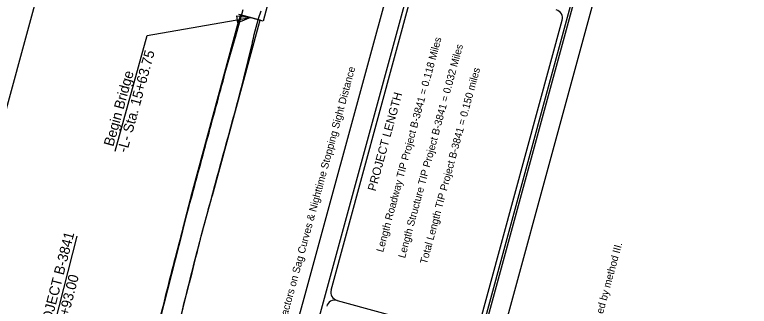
# Model space of a CAD drawing. Extents: x 2076126 to 2079903, y 925480 to 928006.
# Drawn here: x 2079033 to 2079903, y 926068 to 926413 of the extents above; entities that cross this region are included whole.
import ezdxf

# ---------------------------------------------------------------- set-up
doc = ezdxf.new("R2010")
doc.units = 0
for name, color, linetype in [('Default', 7, 'Continuous'), ('Old_Level_3', 7, 'Continuous'), ('Prop EOT', 7, 'Continuous'), ('Prop Horizontal Alignment Curve and Spiral Data', 7, 'Continuous'), ('Prop Roadway Bridge', 7, 'Continuous'), ('Prop Shade Heavy', 7, 'Continuous'), ('Prop Shade Medium', 7, 'Continuous'), ('Sheet Data Field CELL', 7, 'Continuous'), ('Sheet Plot Border Inside CELL', 7, 'Continuous'), ('Sheet Plot Border Outside CELL', 7, 'Continuous'), ('Sheet Title CELL', 7, 'Continuous')]:
    doc.layers.add(name, color=color, linetype=linetype)

msp = doc.modelspace()

# ---------------------------------------------------------------- linework, layer by layer
at = {"layer": 'Default'}
msp.add_line((2079152.14, 926251.6), (2079189.95, 926388.47), dxfattribs=at)
msp.add_lwpolyline([(2079189.95, 926388.47), (2079312.25, 926409.91)], dxfattribs=at)
msp.add_lwpolyline([(2079296.36, 926411.79), (2079312.25, 926409.91), (2079297.55, 926403.59)], close=True, dxfattribs=at)
at = {"layer": 'Old_Level_3'}
for p, q in [((2079282.55, 926344.59), (2079294.11, 926385.17)), ((2079304.56, 926338.12), (2079314.61, 926379.68))]:
    msp.add_line(p, q, dxfattribs=at)
for points in [[(2079294.11, 926385.17), (2079294.48, 926386.49), (2079303.66, 926419.15)], [(2079314.61, 926379.68), (2079314.76, 926380.22), (2079314.9, 926380.86)]]:
    msp.add_lwpolyline(points, dxfattribs=at)
for points in [[(2079314.9, 926380.86), (2079324.11, 926415.38), (2079324.96, 926417.77)], [(2079188.92, 925968.28), (2079196.1, 926009.76), (2079205.39, 926053.24), (2079215.66, 926095.07), (2079226.53, 926137.47), (2079237.81, 926179.58), (2079249.18, 926221.19), (2079260.41, 926263), (2079271.8, 926304.79), (2079282.55, 926344.59)], [(2079212.37, 925965.4), (2079219.2, 926006.07), (2079228.11, 926047.86), (2079238.24, 926089.55), (2079248.89, 926131.69), (2079259.94, 926173.18), (2079271.27, 926214.87), (2079282.61, 926256.56), (2079294.09, 926298.22), (2079304.56, 926338.12)]]:
    msp.add_spline(points, degree=3, dxfattribs=at)
at = {"layer": 'Prop EOT'}
for p, q in [((2079244.04, 926205.43), (2079298.76, 926406.07)), ((2079267.19, 926199.11), (2079321.92, 926399.75))]:
    msp.add_line(p, q, dxfattribs=at)
for points in [[(2079231.67, 926156.83), (2079231.83, 926157.49), (2079232, 926158.16), (2079232.16, 926158.82), (2079232.32, 926159.49), (2079232.48, 926160.15), (2079232.65, 926160.81), (2079232.81, 926161.48), (2079232.98, 926162.14), (2079233.14, 926162.8), (2079233.31, 926163.47), (2079233.48, 926164.13), (2079233.64, 926164.79), (2079233.81, 926165.45), (2079233.98, 926166.12), (2079234.14, 926166.78), (2079234.31, 926167.44), (2079234.48, 926168.1), (2079234.65, 926168.77), (2079234.82, 926169.42), (2079234.99, 926170.08), (2079235.15, 926170.73), (2079235.32, 926171.39), (2079235.49, 926172.04), (2079235.66, 926172.69), (2079235.82, 926173.35), (2079235.99, 926174), (2079236.16, 926174.66), (2079236.33, 926175.31), (2079236.5, 926175.97), (2079236.66, 926176.62), (2079236.83, 926177.28), (2079237, 926177.93), (2079237.17, 926178.59), (2079237.33, 926179.24), (2079237.5, 926179.9), (2079237.67, 926180.55), (2079237.84, 926181.21), (2079238, 926181.86), (2079238.17, 926182.51), (2079238.34, 926183.17), (2079238.51, 926183.82), (2079238.67, 926184.48), (2079238.84, 926185.13), (2079239.01, 926185.79), (2079239.18, 926186.44), (2079239.34, 926187.1), (2079239.51, 926187.75), (2079239.68, 926188.41), (2079239.85, 926189.06), (2079240.01, 926189.72), (2079240.18, 926190.37), (2079240.35, 926191.02), (2079240.52, 926191.68), (2079240.69, 926192.33), (2079240.85, 926192.99), (2079241.02, 926193.64), (2079241.19, 926194.3), (2079241.36, 926194.95), (2079241.52, 926195.61), (2079241.69, 926196.26), (2079241.86, 926196.92), (2079242.03, 926197.57), (2079242.19, 926198.23), (2079242.36, 926198.88), (2079242.53, 926199.54), (2079242.7, 926200.19), (2079242.86, 926200.84), (2079243.03, 926201.5), (2079243.2, 926202.15), (2079243.37, 926202.81), (2079243.53, 926203.46), (2079243.7, 926204.12), (2079244.04, 926205.43)], [(2079253.99, 926151.04), (2079254.16, 926151.68), (2079254.33, 926152.33), (2079254.5, 926152.97), (2079254.68, 926153.62), (2079254.85, 926154.26), (2079255.02, 926154.91), (2079255.19, 926155.55), (2079255.37, 926156.2), (2079255.54, 926156.84), (2079255.71, 926157.49), (2079255.89, 926158.13), (2079256.06, 926158.78), (2079256.24, 926159.42), (2079256.41, 926160.06), (2079256.59, 926160.71), (2079256.77, 926161.35), (2079256.94, 926162), (2079257.12, 926162.64), (2079257.3, 926163.29), (2079257.48, 926163.94), (2079257.66, 926164.59), (2079257.84, 926165.24), (2079258.02, 926165.9), (2079258.2, 926166.55), (2079258.38, 926167.2), (2079258.56, 926167.85), (2079258.74, 926168.5), (2079258.92, 926169.15), (2079259.1, 926169.8), (2079259.28, 926170.45), (2079259.46, 926171.11), (2079259.64, 926171.76), (2079259.82, 926172.41), (2079260, 926173.06), (2079260.18, 926173.71), (2079260.36, 926174.36), (2079260.54, 926175.01), (2079260.72, 926175.66), (2079260.9, 926176.32), (2079261.08, 926176.97), (2079261.26, 926177.62), (2079261.44, 926178.27), (2079261.62, 926178.92), (2079261.8, 926179.57), (2079261.98, 926180.22), (2079262.16, 926180.88), (2079262.34, 926181.53), (2079262.52, 926182.18), (2079262.7, 926182.83), (2079262.88, 926183.48), (2079263.06, 926184.13), (2079263.23, 926184.78), (2079263.41, 926185.43), (2079263.59, 926186.09), (2079263.77, 926186.74), (2079263.95, 926187.39), (2079264.13, 926188.04), (2079264.31, 926188.69), (2079264.49, 926189.34), (2079264.67, 926189.99), (2079264.85, 926190.64), (2079265.03, 926191.3), (2079265.21, 926191.95), (2079265.39, 926192.6), (2079265.57, 926193.25), (2079265.75, 926193.9), (2079265.93, 926194.55), (2079266.11, 926195.2), (2079266.29, 926195.86), (2079266.47, 926196.51), (2079266.65, 926197.16), (2079266.83, 926197.81), (2079267.19, 926199.11)]]:
    msp.add_spline(points, degree=3, dxfattribs=at)
at = {"layer": 'Prop Horizontal Alignment Curve and Spiral Data'}
msp.add_line((2079106.69, 926150.93), (2079048.26, 925923.65), dxfattribs=at)
at = {"layer": 'Prop Roadway Bridge'}
msp.add_lwpolyline([(2078921.55, 925929.3), (2079234.74, 927077.57), (2079619.8, 926972.54), (2079306.61, 925824.27)], close=True, dxfattribs=at)
at = {"layer": 'Prop Shade Heavy'}
for p, q in [((2079370.28, 926564.98), (2079327.47, 926405.63)), ((2079327.47, 926405.63), (2079298.5, 926413.42))]:
    msp.add_line(p, q, dxfattribs=at)
at = {"layer": 'Prop Shade Medium'}
for points in [[(2079321.92, 926399.75), (2079323.79, 926406.62), (2079300.61, 926412.85), (2079298.76, 926406.07), (2079244.04, 926205.43)], [(2079267.19, 926199.11), (2079321.92, 926399.75)], [(2079231.67, 926156.83), (2079205.44, 926053.45), (2079228.09, 926047.79)]]:
    msp.add_lwpolyline(points, dxfattribs=at)
for points in [[(2079244.04, 926205.43), (2079243.93, 926204.99), (2079243.81, 926204.55), (2079243.7, 926204.12), (2079243.65, 926203.9), (2079243.59, 926203.68), (2079243.53, 926203.46), (2079243.48, 926203.24), (2079243.42, 926203.03), (2079243.37, 926202.81), (2079243.31, 926202.59), (2079243.26, 926202.37), (2079243.2, 926202.15), (2079243.14, 926201.94), (2079243.09, 926201.72), (2079243.03, 926201.5), (2079242.98, 926201.28), (2079242.92, 926201.06), (2079242.86, 926200.84), (2079242.81, 926200.63), (2079242.75, 926200.41), (2079242.7, 926200.19), (2079242.64, 926199.97), (2079242.59, 926199.75), (2079242.53, 926199.54), (2079242.47, 926199.32), (2079242.42, 926199.1), (2079242.36, 926198.88), (2079242.31, 926198.66), (2079242.25, 926198.44), (2079242.19, 926198.23), (2079242.14, 926198.01), (2079242.08, 926197.79), (2079242.03, 926197.57), (2079241.97, 926197.35), (2079241.91, 926197.13), (2079241.86, 926196.92), (2079241.8, 926196.7), (2079241.75, 926196.48), (2079241.69, 926196.26), (2079241.64, 926196.04), (2079241.58, 926195.83), (2079241.52, 926195.61), (2079241.47, 926195.39), (2079241.41, 926195.17), (2079241.36, 926194.95), (2079241.3, 926194.73), (2079241.24, 926194.52), (2079241.19, 926194.3), (2079241.13, 926194.08), (2079241.08, 926193.86), (2079241.02, 926193.64), (2079240.96, 926193.43), (2079240.91, 926193.21), (2079240.85, 926192.99), (2079240.8, 926192.77), (2079240.74, 926192.55), (2079240.69, 926192.33), (2079240.63, 926192.12), (2079240.57, 926191.9), (2079240.52, 926191.68), (2079240.46, 926191.46), (2079240.41, 926191.24), (2079240.35, 926191.02), (2079240.29, 926190.81), (2079240.24, 926190.59), (2079240.18, 926190.37), (2079240.13, 926190.15), (2079240.07, 926189.93), (2079240.01, 926189.72), (2079239.96, 926189.5), (2079239.9, 926189.28), (2079239.85, 926189.06), (2079239.79, 926188.84), (2079239.74, 926188.62), (2079239.68, 926188.41), (2079239.62, 926188.19), (2079239.57, 926187.97), (2079239.51, 926187.75), (2079239.46, 926187.53), (2079239.4, 926187.32), (2079239.34, 926187.1), (2079239.29, 926186.88), (2079239.23, 926186.66), (2079239.18, 926186.44), (2079239.12, 926186.22), (2079239.07, 926186.01), (2079239.01, 926185.79), (2079238.95, 926185.57), (2079238.9, 926185.35), (2079238.84, 926185.13), (2079238.79, 926184.91), (2079238.73, 926184.7), (2079238.67, 926184.48), (2079238.62, 926184.26), (2079238.56, 926184.04), (2079238.51, 926183.82), (2079238.45, 926183.61), (2079238.39, 926183.39), (2079238.34, 926183.17), (2079238.28, 926182.95), (2079238.23, 926182.73), (2079238.17, 926182.51), (2079238.12, 926182.3), (2079238.06, 926182.08), (2079238, 926181.86), (2079237.95, 926181.64), (2079237.89, 926181.42), (2079237.84, 926181.21), (2079237.78, 926180.99), (2079237.72, 926180.77), (2079237.67, 926180.55), (2079237.61, 926180.33), (2079237.56, 926180.11), (2079237.5, 926179.9), (2079237.44, 926179.68), (2079237.39, 926179.46), (2079237.33, 926179.24), (2079237.28, 926179.02), (2079237.22, 926178.8), (2079237.17, 926178.59), (2079237.11, 926178.37), (2079237.05, 926178.15), (2079237, 926177.93), (2079236.94, 926177.71), (2079236.89, 926177.5), (2079236.83, 926177.28), (2079236.77, 926177.06), (2079236.72, 926176.84), (2079236.66, 926176.62), (2079236.61, 926176.4), (2079236.55, 926176.19), (2079236.5, 926175.97), (2079236.44, 926175.75), (2079236.38, 926175.53), (2079236.33, 926175.31), (2079236.27, 926175.1), (2079236.22, 926174.88), (2079236.16, 926174.66), (2079236.1, 926174.44), (2079236.05, 926174.22), (2079235.99, 926174), (2079235.94, 926173.79), (2079235.88, 926173.57), (2079235.82, 926173.35), (2079235.77, 926173.13), (2079235.71, 926172.91), (2079235.66, 926172.69), (2079235.6, 926172.48), (2079235.55, 926172.26), (2079235.49, 926172.04), (2079235.43, 926171.82), (2079235.38, 926171.6), (2079235.32, 926171.39), (2079235.27, 926171.17), (2079235.21, 926170.95), (2079235.15, 926170.73), (2079235.1, 926170.51), (2079235.04, 926170.29), (2079234.99, 926170.08), (2079234.93, 926169.86), (2079234.87, 926169.64), (2079234.82, 926169.42), (2079234.76, 926169.2), (2079234.71, 926168.98), (2079234.65, 926168.77), (2079234.59, 926168.55), (2079234.54, 926168.32), (2079234.48, 926168.1), (2079234.43, 926167.88), (2079234.37, 926167.66), (2079234.31, 926167.44), (2079234.26, 926167.22), (2079234.2, 926167), (2079234.14, 926166.78), (2079234.09, 926166.56), (2079234.03, 926166.34), (2079233.98, 926166.12), (2079233.92, 926165.9), (2079233.86, 926165.67), (2079233.81, 926165.45), (2079233.75, 926165.23), (2079233.7, 926165.01), (2079233.64, 926164.79), (2079233.59, 926164.57), (2079233.53, 926164.35), (2079233.48, 926164.13), (2079233.42, 926163.91), (2079233.36, 926163.69), (2079233.31, 926163.47), (2079233.25, 926163.24), (2079233.2, 926163.02), (2079233.14, 926162.8), (2079233.09, 926162.58), (2079233.03, 926162.36), (2079232.98, 926162.14), (2079232.92, 926161.92), (2079232.87, 926161.7), (2079232.81, 926161.48), (2079232.76, 926161.26), (2079232.7, 926161.03), (2079232.65, 926160.81), (2079232.59, 926160.59), (2079232.54, 926160.37), (2079232.48, 926160.15), (2079232.43, 926159.93), (2079232.38, 926159.71), (2079232.32, 926159.49), (2079232.27, 926159.26), (2079232.21, 926159.04), (2079232.16, 926158.82), (2079232.1, 926158.6), (2079232.05, 926158.38), (2079232, 926158.16), (2079231.94, 926157.94), (2079231.89, 926157.72), (2079231.83, 926157.49), (2079231.78, 926157.27), (2079231.73, 926157.05), (2079231.67, 926156.83)], [(2079228.09, 926047.79), (2079254.05, 926151.25), (2079254.11, 926151.47), (2079254.16, 926151.68), (2079254.22, 926151.9), (2079254.28, 926152.11), (2079254.33, 926152.33), (2079254.39, 926152.54), (2079254.45, 926152.76), (2079254.5, 926152.97), (2079254.56, 926153.19), (2079254.62, 926153.4), (2079254.68, 926153.62), (2079254.73, 926153.83), (2079254.79, 926154.05), (2079254.85, 926154.26), (2079254.9, 926154.48), (2079254.96, 926154.69), (2079255.02, 926154.91), (2079255.08, 926155.12), (2079255.13, 926155.34), (2079255.19, 926155.55), (2079255.25, 926155.77), (2079255.31, 926155.98), (2079255.37, 926156.2), (2079255.42, 926156.41), (2079255.48, 926156.63), (2079255.54, 926156.84), (2079255.6, 926157.06), (2079255.65, 926157.27), (2079255.71, 926157.49), (2079255.77, 926157.7), (2079255.83, 926157.92), (2079255.89, 926158.13), (2079255.95, 926158.35), (2079256, 926158.56), (2079256.06, 926158.78), (2079256.12, 926158.99), (2079256.18, 926159.21), (2079256.24, 926159.42), (2079256.3, 926159.64), (2079256.35, 926159.85), (2079256.41, 926160.06), (2079256.47, 926160.28), (2079256.53, 926160.49), (2079256.59, 926160.71), (2079256.65, 926160.92), (2079256.71, 926161.14), (2079256.77, 926161.35), (2079256.82, 926161.57), (2079256.88, 926161.78), (2079256.94, 926162), (2079257, 926162.21), (2079257.06, 926162.43), (2079257.12, 926162.64), (2079257.18, 926162.86), (2079257.24, 926163.07), (2079257.3, 926163.29), (2079257.36, 926163.51), (2079257.42, 926163.72), (2079257.48, 926163.94), (2079257.54, 926164.16), (2079257.6, 926164.38), (2079257.66, 926164.59), (2079257.72, 926164.81), (2079257.78, 926165.03), (2079257.84, 926165.24), (2079257.9, 926165.46), (2079257.96, 926165.68), (2079258.02, 926165.9), (2079258.08, 926166.11), (2079258.14, 926166.33), (2079258.2, 926166.55), (2079258.26, 926166.76), (2079258.32, 926166.98), (2079258.38, 926167.2), (2079258.44, 926167.41), (2079258.5, 926167.63), (2079258.56, 926167.85), (2079258.62, 926168.07), (2079258.68, 926168.28), (2079258.74, 926168.5), (2079258.8, 926168.72), (2079258.86, 926168.93), (2079258.92, 926169.15), (2079258.98, 926169.37), (2079259.04, 926169.59), (2079259.1, 926169.8), (2079259.16, 926170.02), (2079259.22, 926170.24), (2079259.28, 926170.45), (2079259.34, 926170.67), (2079259.4, 926170.89), (2079259.46, 926171.11), (2079259.52, 926171.32), (2079259.58, 926171.54), (2079259.64, 926171.76), (2079259.7, 926171.97), (2079259.76, 926172.19), (2079259.82, 926172.41), (2079259.88, 926172.63), (2079259.94, 926172.84), (2079260, 926173.06), (2079260.06, 926173.28), (2079260.12, 926173.49), (2079260.18, 926173.71), (2079260.24, 926173.93), (2079260.3, 926174.14), (2079260.36, 926174.36), (2079260.42, 926174.58), (2079260.48, 926174.8), (2079260.54, 926175.01), (2079260.6, 926175.23), (2079260.66, 926175.45), (2079260.72, 926175.66), (2079260.78, 926175.88), (2079260.84, 926176.1), (2079260.9, 926176.32), (2079260.96, 926176.53), (2079261.02, 926176.75), (2079261.08, 926176.97), (2079261.14, 926177.18), (2079261.2, 926177.4), (2079261.26, 926177.62), (2079261.32, 926177.84), (2079261.38, 926178.05), (2079261.44, 926178.27), (2079261.5, 926178.49), (2079261.56, 926178.7), (2079261.62, 926178.92), (2079261.68, 926179.14), (2079261.74, 926179.36), (2079261.8, 926179.57), (2079261.86, 926179.79), (2079261.92, 926180.01), (2079261.98, 926180.22), (2079262.04, 926180.44), (2079262.1, 926180.66), (2079262.16, 926180.88), (2079262.22, 926181.09), (2079262.28, 926181.31), (2079262.34, 926181.53), (2079262.4, 926181.74), (2079262.46, 926181.96), (2079262.52, 926182.18), (2079262.58, 926182.39), (2079262.64, 926182.61), (2079262.7, 926182.83), (2079262.76, 926183.05), (2079262.82, 926183.26), (2079262.88, 926183.48), (2079262.94, 926183.7), (2079263, 926183.91), (2079263.06, 926184.13), (2079263.12, 926184.35), (2079263.18, 926184.57), (2079263.23, 926184.78), (2079263.29, 926185), (2079263.35, 926185.22), (2079263.41, 926185.43), (2079263.47, 926185.65), (2079263.53, 926185.87), (2079263.59, 926186.09), (2079263.65, 926186.3), (2079263.71, 926186.52), (2079263.77, 926186.74), (2079263.83, 926186.95), (2079263.89, 926187.17), (2079263.95, 926187.39), (2079264.01, 926187.61), (2079264.07, 926187.82), (2079264.13, 926188.04), (2079264.19, 926188.26), (2079264.25, 926188.47), (2079264.31, 926188.69), (2079264.37, 926188.91), (2079264.43, 926189.12), (2079264.49, 926189.34), (2079264.55, 926189.56), (2079264.61, 926189.78), (2079264.67, 926189.99), (2079264.73, 926190.21), (2079264.79, 926190.43), (2079264.85, 926190.64), (2079264.91, 926190.86), (2079264.97, 926191.08), (2079265.03, 926191.3), (2079265.09, 926191.51), (2079265.15, 926191.73), (2079265.21, 926191.95), (2079265.27, 926192.16), (2079265.33, 926192.38), (2079265.39, 926192.6), (2079265.45, 926192.82), (2079265.51, 926193.03), (2079265.57, 926193.25), (2079265.63, 926193.47), (2079265.69, 926193.68), (2079265.75, 926193.9), (2079265.81, 926194.12), (2079265.87, 926194.34), (2079265.93, 926194.55), (2079265.99, 926194.77), (2079266.05, 926194.99), (2079266.11, 926195.2), (2079266.17, 926195.42), (2079266.23, 926195.64), (2079266.29, 926195.86), (2079266.35, 926196.07), (2079266.41, 926196.29), (2079266.47, 926196.51), (2079266.53, 926196.72), (2079266.59, 926196.94), (2079266.65, 926197.16), (2079266.71, 926197.37), (2079266.77, 926197.59), (2079266.83, 926197.81), (2079266.95, 926198.24), (2079267.07, 926198.68), (2079267.19, 926199.11)]]:
    msp.add_open_spline(points, degree=3, dxfattribs=at)
at = {"layer": 'Sheet Plot Border Inside CELL'}
msp.add_lwpolyline([(2079441.8, 925498.58), (2079880.32, 927106.35), (2078862.41, 927383.99), (2078423.88, 925776.22)], close=True, dxfattribs=at)
at = {"layer": 'Sheet Plot Border Outside CELL'}
msp.add_lwpolyline([(2078841.94, 927394.24), (2078398.8, 925769.59), (2079460.02, 925480.14), (2079903.16, 927104.79)], close=True, dxfattribs=at)
at = {"layer": 'Sheet Title CELL'}
for p, q in [((2079313.65, 925760.54), (2079687.31, 927130.49)), ((2079407.95, 926087.23), (2079507.95, 926453.84)), ((2079414.96, 926074.96), (2079569.32, 926032.86))]:
    msp.add_line(p, q, dxfattribs=at)
for points in [[(2079482.49, 925657.47), (2079871.94, 927085.31)], [(2079581.61, 926039.87), (2079681.6, 926406.48)]]:
    msp.add_lwpolyline(points, dxfattribs=at)
for centre, start, end in [((2079671.9, 926409.13), 344.7434, 74.7434), ((2079417.55, 926084.62), 164.7434, 254.7434), ((2079412.29, 926065.33), 74.7434, 164.7434)]:
    msp.add_arc(centre, 10, start, end, dxfattribs=at)

# ---------------------------------------------------------------- texts
at = {"layer": 'Default'}
for s, height, rotation, p in [('-L- Sta. 15+63.75', 12, 74.55721, (2079166.02, 926249.22)), ('NOTE: Design Exception Required for K Factors on Sag Curves & Nighttime Stopping Sight Distance', 8.7501, 74.7434, (2079298.81, 925845.26)), ('Begin Bridge', 12, 74.55721, (2079149.83, 926256.4)), ('BEGIN TIP PROJECT B-3841', 12, 75.58093, (2079050.31, 925946.2)), ('Clearing on this project shall be performed to the limits established by method III.', 8.7501, 74.7434, (2079642.57, 925738.41)), ('-L- POC STA 11+93.00', 12, 75.58093, (2079067.77, 925942.68))]:
    msp.add_text(s, height=height, rotation=rotation, dxfattribs=at).set_placement(p)
at = {"layer": 'Sheet Data Field CELL'}
for s, p in [('Length Roadway TIP Project B-3841 = 0.118 Miles', (2079469.48, 926131.4)), ('Length Structure TIP Project B-3841 = 0.032 Miles', (2079495.38, 926124.34)), ('Total Length TIP Project B-3841 = 0.150 miles', (2079521.25, 926117.28))]:
    msp.add_text(s, height=8.7501, rotation=74.7434, dxfattribs=at).set_placement(p)
at = {"layer": 'Sheet Title CELL'}
msp.add_text('PROJECT LENGTH', height=9.9996, rotation=74.7434, dxfattribs=at).set_placement((2079460.56, 926203.59))

doc.saveas('drawing.dxf')
